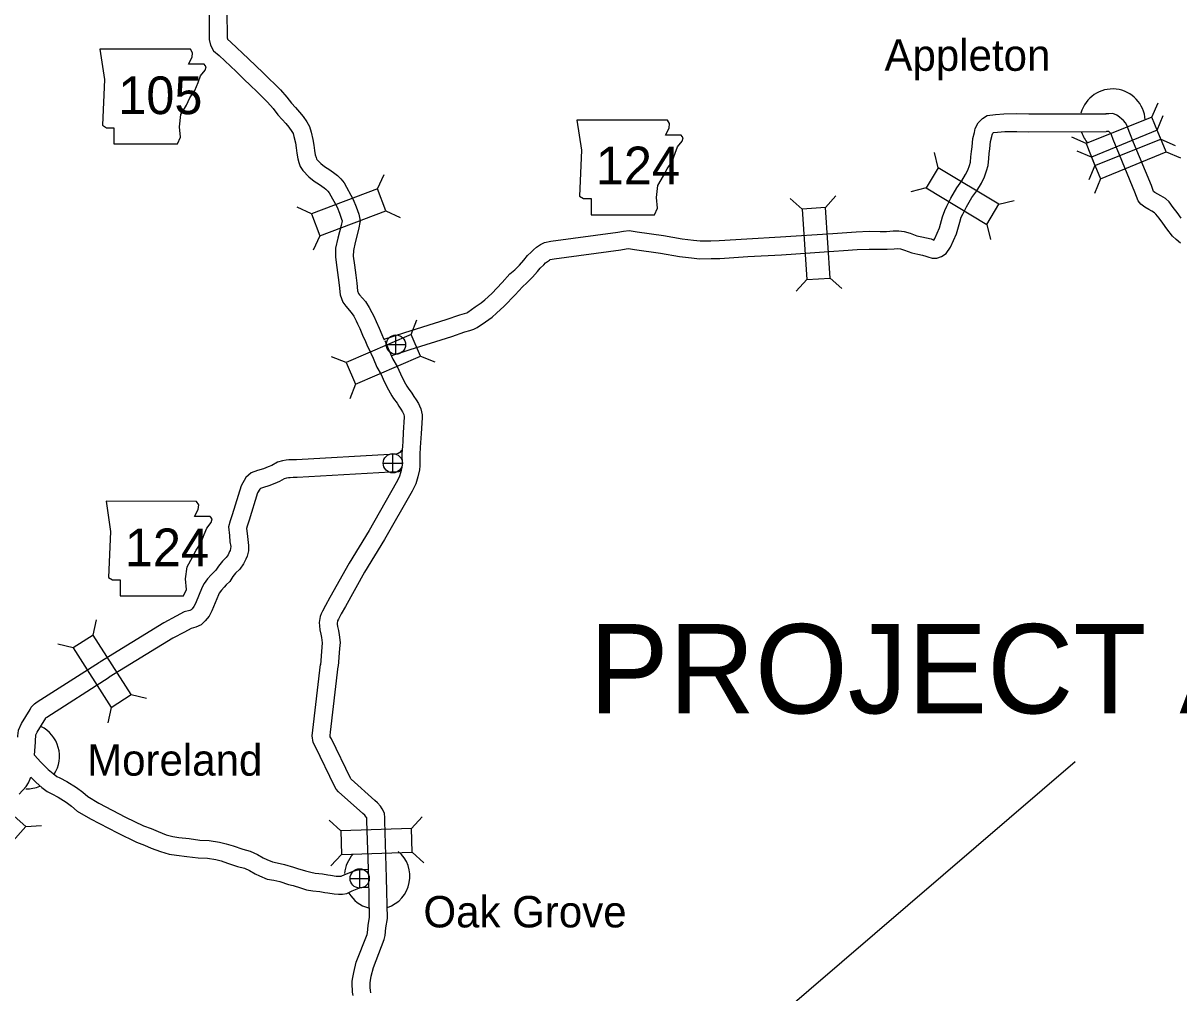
# Model space of a CAD drawing. Extents: x 1374139 to 1377472, y 1168351 to 1170484.
# Drawn here: x 1374734 to 1374928.1, y 1170176.4 to 1170339.4 of the extents above; entities that cross this region are included whole.
import ezdxf

# ---------------------------------------------------------------- set-up
doc = ezdxf.new("R2010")
doc.units = 0
doc.layers.add('15', color=7, linetype='Continuous')
doc.layers.add('Default', color=7, linetype='Continuous')

msp = doc.modelspace()

# ---------------------------------------------------------------- linework, layer by layer
at = {"layer": '15'}
msp.add_line((1374910.7, 1170215.21), (1374680.58, 1170017.86), dxfattribs=at)
at = {"layer": 'Default'}
for p, q in [((1374923.61, 1170323.53), (1374924.65, 1170325.95)), ((1374924.46, 1170321.38), (1374925.47, 1170323.82)), ((1374912.57, 1170319.13), (1374910.15, 1170320.17)), ((1374925.08, 1170319.85), (1374927.5, 1170318.81)), ((1374887.7, 1170315.05), (1374887.06, 1170317.61)), ((1374913.48, 1170316.85), (1374911.04, 1170317.86)), ((1374925.97, 1170317.72), (1374928.41, 1170316.71)), ((1374914.04, 1170315.45), (1374913, 1170313.02)), ((1374793.52, 1170311.5), (1374794.61, 1170313.91)), ((1374914.99, 1170313.19), (1374913.98, 1170310.75)), ((1374885.66, 1170311.66), (1374883.1, 1170311.02)), ((1374864.83, 1170308.12), (1374862.85, 1170309.87)), ((1374868.78, 1170308.38), (1374870.52, 1170310.36)), ((1374897.88, 1170308.93), (1374900.44, 1170309.57)), ((1374782.39, 1170307.32), (1374779.99, 1170308.41)), ((1374794.91, 1170307.8), (1374797.31, 1170306.71)), ((1374895.84, 1170305.54), (1374896.48, 1170302.98)), ((1374783.79, 1170303.62), (1374782.7, 1170301.21)), ((1374865.6, 1170296.27), (1374863.86, 1170294.29)), ((1374869.55, 1170296.52), (1374871.53, 1170294.78)), ((1374799.13, 1170287.04), (1374800.1, 1170289.49)), ((1374796.59, 1170283.71), (1374796.59, 1170286.96)), ((1374794.97, 1170285.33), (1374798.22, 1170285.33)), ((1374788.22, 1170282.32), (1374785.77, 1170283.29)), ((1374800.7, 1170283.4), (1374803.15, 1170282.43)), ((1374789.79, 1170278.69), (1374788.82, 1170276.23)), ((1374796.07, 1170263.78), (1374796.07, 1170267.03)), ((1374794.44, 1170265.4), (1374797.69, 1170265.4)), ((1374745.7, 1170236.53), (1374746.27, 1170239.11)), ((1374742.36, 1170234.4), (1374739.78, 1170234.97)), ((1374752.08, 1170226.51), (1374754.66, 1170225.94)), ((1374748.74, 1170224.38), (1374748.17, 1170221.8)), ((1374734.39, 1170204.34), (1374737.03, 1170204.5)), ((1374787.31, 1170203.63), (1374785.38, 1170205.43)), ((1374799.18, 1170204.03), (1374800.99, 1170205.96)), ((1374787.44, 1170199.67), (1374785.64, 1170197.74)), ((1374799.32, 1170200.07), (1374801.25, 1170198.27)), ((1374790.5, 1170194.01), (1374790.5, 1170197.26)), ((1374788.87, 1170195.63), (1374792.12, 1170195.63))]:
    msp.add_line(p, q, dxfattribs=at)
for points in [[(1374765.19, 1170341.33), (1374765.23, 1170336.62), (1374765.41, 1170335.64), (1374765.95, 1170334.69), (1374766.87, 1170333.93), (1374769.73, 1170331.2), (1374770.96, 1170330.01), (1374772.22, 1170328.84), (1374773.14, 1170327.91), (1374774.16, 1170326.9), (1374775.01, 1170326.06), (1374775.97, 1170325.01), (1374776.77, 1170323.95), (1374777.49, 1170323.18), (1374778.09, 1170322.48), (1374778.61, 1170321.85), (1374779.12, 1170321.13), (1374779.31, 1170320.79), (1374779.46, 1170320.28), (1374779.69, 1170319.23), (1374779.84, 1170318.41), (1374779.94, 1170317.51), (1374780.12, 1170316.54), (1374780.3, 1170315.91), (1374780.5, 1170315.27), (1374780.93, 1170314.57), (1374781.96, 1170313.51), (1374782.86, 1170312.82), (1374783.76, 1170312.26), (1374784.51, 1170311.68), (1374784.82, 1170311.45), (1374785.14, 1170311.14), (1374785.4, 1170310.84), (1374786.71, 1170308.43), (1374787.1, 1170307.42), (1374787.47, 1170306.43), (1374787.54, 1170306.12), (1374787.39, 1170305.33), (1374786.84, 1170303.23), (1374786.45, 1170301.55), (1374786.42, 1170300.04), (1374786.65, 1170298.3), (1374786.87, 1170296.62), (1374787.04, 1170295.31), (1374787.21, 1170293.67), (1374787.67, 1170292.48), (1374788.15, 1170291.82), (1374789.08, 1170290.75), (1374789.5, 1170290.09), (1374789.89, 1170289.34), (1374790.16, 1170288.83), (1374790.52, 1170288.03), (1374791, 1170286.92), (1374791.45, 1170285.87), (1374791.82, 1170285.01), (1374792.03, 1170284.65)], [(1374768.19, 1170341.35), (1374768.22, 1170336.91), (1374768.27, 1170336.69), (1374768.29, 1170336.65), (1374768.87, 1170336.17), (1374771.81, 1170333.36), (1374773.03, 1170332.19), (1374774.3, 1170330.99), (1374775.26, 1170330.04), (1374776.28, 1170329.03), (1374777.17, 1170328.13), (1374778.28, 1170326.93), (1374779.07, 1170325.88), (1374779.72, 1170325.18), (1374780.39, 1170324.41), (1374781, 1170323.66), (1374781.64, 1170322.75), (1374782.09, 1170321.98), (1374782.37, 1170321.02), (1374782.64, 1170319.81), (1374782.81, 1170318.84), (1374782.91, 1170317.96), (1374783.04, 1170317.22), (1374783.17, 1170316.77), (1374783.25, 1170316.53), (1374783.31, 1170316.42), (1374783.96, 1170315.76), (1374784.57, 1170315.28), (1374785.47, 1170314.73), (1374786.31, 1170314.08), (1374786.75, 1170313.76), (1374787.34, 1170313.19), (1374787.89, 1170312.53), (1374789.43, 1170309.7), (1374789.9, 1170308.49), (1374790.36, 1170307.27), (1374790.59, 1170306.14), (1374790.31, 1170304.68), (1374789.75, 1170302.51), (1374789.44, 1170301.17), (1374789.42, 1170300.21), (1374789.62, 1170298.69), (1374789.84, 1170297.01), (1374790.02, 1170295.67), (1374790.16, 1170294.37), (1374790.32, 1170293.93), (1374790.49, 1170293.7), (1374791.49, 1170292.55), (1374792.11, 1170291.59), (1374792.56, 1170290.72), (1374792.85, 1170290.14), (1374793.26, 1170289.24), (1374793.75, 1170288.11), (1374794.21, 1170287.06), (1374794.51, 1170286.34), (1374794.64, 1170286.12)], [(1374794.64, 1170286.27), (1374798.06, 1170287.36), (1374805.04, 1170289.54), (1374807.3, 1170290.33), (1374808.09, 1170290.54), (1374808.49, 1170290.69), (1374808.66, 1170290.78), (1374809.92, 1170291.66), (1374810.92, 1170292.33), (1374811.51, 1170292.83), (1374812.68, 1170293.91), (1374814.44, 1170295.76), (1374815.74, 1170297.21), (1374816.54, 1170297.9), (1374817.33, 1170298.7), (1374818.06, 1170299.55), (1374818.67, 1170300.28), (1374819.33, 1170300.88), (1374819.7, 1170301.26), (1374820.22, 1170301.7), (1374820.88, 1170302.16), (1374821.57, 1170302.47), (1374822.63, 1170302.71), (1374833.87, 1170304.22), (1374834.85, 1170304.41), (1374835.77, 1170304.5), (1374837.12, 1170304.29), (1374841.53, 1170303.66), (1374844.68, 1170303.09), (1374846.57, 1170302.88), (1374847.71, 1170302.77), (1374849.5, 1170302.8), (1374850.9, 1170302.82), (1374855.54, 1170303.11), (1374861.18, 1170303.44), (1374869.98, 1170304.01), (1374871.58, 1170304.11), (1374873.9, 1170304.29), (1374876.08, 1170304.39), (1374877.93, 1170304.36), (1374879.03, 1170304.36), (1374880.14, 1170304.45), (1374881.09, 1170304.48), (1374882, 1170304.34), (1374882.96, 1170304.06), (1374884.13, 1170303.63), (1374884.92, 1170303.44), (1374885.71, 1170303.28), (1374886.5, 1170303.09), (1374886.97, 1170302.91), (1374887.12, 1170303.14), (1374887.92, 1170304.97), (1374888.44, 1170306.8), (1374888.79, 1170307.85), (1374889.12, 1170308.58), (1374889.81, 1170309.94), (1374890.85, 1170311.67), (1374891.67, 1170312.83), (1374892.31, 1170313.91), (1374892.68, 1170314.67), (1374892.95, 1170315.43), (1374893.11, 1170316), (1374893.19, 1170316.89), (1374893.29, 1170317.79), (1374893.38, 1170318.57), (1374893.54, 1170319.95), (1374893.77, 1170320.99), (1374893.93, 1170321.66), (1374894.42, 1170322.62), (1374895.12, 1170323.34), (1374895.94, 1170323.86), (1374897.34, 1170324.01), (1374898.72, 1170324.14), (1374900.91, 1170324.16), (1374902.9, 1170324.11), (1374915.93, 1170324.12)], [(1374928.51, 1170306.57), (1374927.85, 1170307.51), (1374927.2, 1170308.38), (1374926.48, 1170309.33), (1374925.86, 1170309.88), (1374925.1, 1170310.35), (1374924.57, 1170310.64), (1374924.12, 1170310.92), (1374923.88, 1170311.09), (1374923.51, 1170312.05), (1374920.52, 1170319.3), (1374919.89, 1170320.87), (1374919.63, 1170321.61), (1374919.46, 1170322.07), (1374919.15, 1170322.59), (1374918.81, 1170322.97), (1374918.55, 1170323.22), (1374918.17, 1170323.58), (1374917.71, 1170323.89), (1374917.03, 1170324.15), (1374916.37, 1170324.14), (1374915.87, 1170324.12)], [(1374795.88, 1170283.51), (1374798.97, 1170284.5), (1374805.98, 1170286.69), (1374808.19, 1170287.46), (1374809.01, 1170287.68), (1374809.7, 1170287.94), (1374810.22, 1170288.21), (1374811.62, 1170289.18), (1374812.74, 1170289.93), (1374813.51, 1170290.6), (1374814.78, 1170291.77), (1374816.64, 1170293.72), (1374817.85, 1170295.06), (1374818.59, 1170295.71), (1374819.54, 1170296.67), (1374820.35, 1170297.62), (1374820.84, 1170298.2), (1374821.42, 1170298.73), (1374821.74, 1170299.06), (1374822.04, 1170299.31), (1374822.38, 1170299.55), (1374822.53, 1170299.61), (1374823.16, 1170299.75), (1374834.36, 1170301.26), (1374835.28, 1170301.43), (1374835.69, 1170301.47), (1374836.68, 1170301.33), (1374841.05, 1170300.7), (1374844.24, 1170300.13), (1374846.27, 1170299.89), (1374847.6, 1170299.77), (1374849.54, 1170299.8), (1374851.01, 1170299.82), (1374855.73, 1170300.12), (1374861.36, 1170300.44), (1374870.17, 1170301.01), (1374871.79, 1170301.12), (1374874.09, 1170301.29), (1374876.12, 1170301.39), (1374877.9, 1170301.36), (1374879.15, 1170301.35), (1374880.32, 1170301.45), (1374880.91, 1170301.47), (1374881.34, 1170301.41), (1374882.02, 1170301.21), (1374883.27, 1170300.75), (1374884.28, 1170300.51), (1374885.05, 1170300.35), (1374885.61, 1170300.22), (1374885.96, 1170300.08), (1374886.67, 1170299.84), (1374887.49, 1170299.88), (1374888.23, 1170300.13), (1374889.06, 1170300.63), (1374889.77, 1170301.7), (1374890.75, 1170303.96), (1374891.31, 1170305.92), (1374891.58, 1170306.75), (1374891.82, 1170307.28), (1374892.43, 1170308.49), (1374893.36, 1170310.03), (1374894.18, 1170311.19), (1374894.95, 1170312.48), (1374895.45, 1170313.51), (1374895.81, 1170314.52), (1374896.07, 1170315.44), (1374896.18, 1170316.6), (1374896.27, 1170317.45), (1374896.36, 1170318.22), (1374896.5, 1170319.46), (1374896.69, 1170320.31), (1374896.76, 1170320.61), (1374896.89, 1170320.85), (1374896.99, 1170320.95), (1374897.64, 1170321.02), (1374898.88, 1170321.14), (1374900.89, 1170321.16), (1374902.86, 1170321.11), (1374915.93, 1170321.12)], [(1374928.38, 1170302.37), (1374927.68, 1170302.97), (1374927.07, 1170303.55), (1374926.1, 1170304.78), (1374925.42, 1170305.74), (1374924.8, 1170306.57), (1374924.27, 1170307.28), (1374924.05, 1170307.47), (1374923.6, 1170307.75), (1374923.07, 1170308.03), (1374922.43, 1170308.43), (1374921.75, 1170308.94), (1374921.27, 1170309.51), (1374920.73, 1170310.94), (1374917.74, 1170318.17), (1374917.08, 1170319.82), (1374916.81, 1170320.59), (1374916.74, 1170320.77), (1374916.73, 1170320.8), (1374916.65, 1170320.88), (1374916.47, 1170321.06), (1374916.39, 1170321.13), (1374915.99, 1170321.12)], [(1374794.7, 1170286), (1374795.48, 1170284.28), (1374796.08, 1170282.9), (1374796.78, 1170281.68), (1374797.35, 1170280.41), (1374797.98, 1170279.11), (1374798.41, 1170278.34), (1374798.63, 1170278.03), (1374799.26, 1170277.16), (1374799.61, 1170276.61), (1374799.97, 1170276.08), (1374800.36, 1170275.43), (1374800.54, 1170275.06), (1374800.76, 1170274.54), (1374800.98, 1170273.56), (1374800.97, 1170273.03), (1374800.81, 1170270.39), (1374800.73, 1170268.85), (1374800.66, 1170268.05), (1374800.59, 1170266.95), (1374800.61, 1170264.98), (1374800.56, 1170264.28), (1374800.28, 1170263.13), (1374799.91, 1170261.96), (1374799.32, 1170260.7), (1374794.67, 1170252.6), (1374791.33, 1170247.09), (1374788.1, 1170241.35), (1374787.4, 1170240.09), (1374786.94, 1170239.19), (1374786.79, 1170238.9), (1374786.79, 1170238.89), (1374786.71, 1170238.47), (1374786.72, 1170238.35), (1374786.77, 1170237.95), (1374786.93, 1170237.32), (1374787.06, 1170236.57), (1374787.2, 1170235.26), (1374787.12, 1170234.25), (1374786.89, 1170231.29)], [(1374791.97, 1170284.76), (1374792.74, 1170283.06), (1374793.39, 1170281.56), (1374794.1, 1170280.31), (1374794.63, 1170279.14), (1374795.32, 1170277.71), (1374795.88, 1170276.72), (1374796.2, 1170276.28), (1374796.78, 1170275.47), (1374797.1, 1170274.97), (1374797.44, 1170274.47), (1374797.71, 1170274.01), (1374797.81, 1170273.81), (1374797.9, 1170273.61), (1374797.97, 1170273.25), (1374797.97, 1170273.14), (1374797.81, 1170270.55), (1374797.74, 1170269.06), (1374797.67, 1170268.28), (1374797.59, 1170267.03), (1374797.61, 1170265.07), (1374797.59, 1170264.75), (1374797.39, 1170263.94), (1374797.11, 1170263.06), (1374796.65, 1170262.09), (1374792.09, 1170254.12), (1374788.74, 1170248.61), (1374785.48, 1170242.81), (1374784.76, 1170241.51), (1374784.27, 1170240.56), (1374784.02, 1170240.07), (1374783.87, 1170239.63), (1374783.7, 1170238.65), (1374783.73, 1170238.07), (1374783.82, 1170237.39), (1374783.99, 1170236.7), (1374784.09, 1170236.14), (1374784.19, 1170235.21), (1374784.13, 1170234.49), (1374783.9, 1170231.52)], [(1374797.65, 1170267.6), (1374797.49, 1170267.46), (1374797.22, 1170267.2), (1374797.22, 1170267.2), (1374796.94, 1170267.05), (1374796.57, 1170266.95), (1374795.49, 1170266.88), (1374779.9, 1170265.99), (1374779.23, 1170265.98), (1374778.62, 1170265.95), (1374778.15, 1170265.9), (1374777.56, 1170265.8), (1374776.67, 1170265.56), (1374775.72, 1170265.03), (1374775.14, 1170264.78), (1374774.32, 1170264.48), (1374773.35, 1170264.19), (1374772.27, 1170263.77), (1374771.38, 1170263), (1374770.57, 1170261.6), (1374769.09, 1170256.73), (1374768.73, 1170255.7), (1374768.47, 1170254.71), (1374768.6, 1170253.28), (1374768.71, 1170252.19), (1374768.83, 1170251.39), (1374768.82, 1170251.07), (1374768.74, 1170250.74), (1374768.65, 1170250.54), (1374768.39, 1170249.99), (1374768.09, 1170249.55), (1374767.43, 1170248.93), (1374766.77, 1170248.1), (1374766.33, 1170247.42), (1374766, 1170247.1), (1374765.54, 1170246.65), (1374764.93, 1170245.97), (1374764.36, 1170245.18), (1374764.04, 1170244.56), (1374762.91, 1170241.85), (1374762.65, 1170241.33), (1374762.34, 1170240.93), (1374762.18, 1170240.78), (1374761.94, 1170240.68), (1374761.02, 1170240.41), (1374759.65, 1170239.68), (1374757.61, 1170238.59), (1374746.83, 1170231.98)], [(1374797.38, 1170264.06), (1374797.08, 1170263.98), (1374795.69, 1170263.88), (1374780.02, 1170262.99), (1374779.33, 1170262.98), (1374778.84, 1170262.96), (1374778.56, 1170262.93), (1374778.21, 1170262.87), (1374777.81, 1170262.76), (1374777.04, 1170262.33), (1374776.24, 1170261.99), (1374775.26, 1170261.63), (1374774.32, 1170261.35), (1374773.84, 1170261.16), (1374773.73, 1170261.06), (1374773.34, 1170260.4), (1374771.94, 1170255.81), (1374771.6, 1170254.82), (1374771.5, 1170254.44), (1374771.58, 1170253.58), (1374771.69, 1170252.57), (1374771.84, 1170251.57), (1374771.81, 1170250.67), (1374771.6, 1170249.79), (1374771.38, 1170249.28), (1374770.98, 1170248.47), (1374770.39, 1170247.61), (1374769.65, 1170246.9), (1374769.21, 1170246.34), (1374768.66, 1170245.5), (1374768.08, 1170244.94), (1374767.71, 1170244.58), (1374767.27, 1170244.08), (1374766.91, 1170243.59), (1374766.76, 1170243.29), (1374765.65, 1170240.61), (1374765.2, 1170239.71), (1374764.56, 1170238.9), (1374763.87, 1170238.25), (1374762.97, 1170237.85), (1374762.16, 1170237.62), (1374761.06, 1170237.03), (1374759.1, 1170235.99), (1374748.4, 1170229.43)], [(1374733.04, 1170219.38), (1374733.09, 1170219.67), (1374733.1, 1170220), (1374733.17, 1170220.57), (1374733.67, 1170221.64), (1374735.14, 1170224.02), (1374735.33, 1170224.39), (1374735.84, 1170224.99), (1374736.32, 1170225.29), (1374746.81, 1170231.97)], [(1374789.41, 1170175.95), (1374789.32, 1170176.49), (1374789.28, 1170177.04), (1374789.26, 1170177.52), (1374789.25, 1170178.36), (1374789.37, 1170178.98), (1374789.5, 1170179.82), (1374789.93, 1170181.58), (1374791.75, 1170186.23), (1374791.82, 1170186.51), (1374791.92, 1170187.71), (1374792.14, 1170189.12), (1374792.02, 1170195.63), (1374791.7, 1170205.29), (1374791.72, 1170205.77), (1374791.7, 1170205.82), (1374791.61, 1170205.93), (1374791.34, 1170206.24), (1374791.01, 1170206.56), (1374786.95, 1170210.17), (1374786.56, 1170210.61), (1374786.27, 1170211.14), (1374783.07, 1170217.74), (1374782.69, 1170218.48), (1374782.5, 1170219.57), (1374782.62, 1170220.57), (1374783.91, 1170231.57)], [(1374735.89, 1170216.33), (1374736.04, 1170218.53), (1374736.03, 1170219.08), (1374736.08, 1170219.38), (1374736.09, 1170219.74), (1374736.31, 1170220.21), (1374737.77, 1170222.56), (1374737.84, 1170222.7), (1374737.92, 1170222.75), (1374748.42, 1170229.44)], [(1374792.37, 1170176.43), (1374792.3, 1170176.85), (1374792.27, 1170177.22), (1374792.26, 1170177.58), (1374792.26, 1170178.1), (1374792.33, 1170178.48), (1374792.44, 1170179.23), (1374792.8, 1170180.67), (1374794.63, 1170185.35), (1374794.79, 1170186.05), (1374794.9, 1170187.35), (1374795.15, 1170188.91), (1374795.02, 1170195.71), (1374794.7, 1170205.28), (1374794.72, 1170205.87), (1374794.65, 1170206.54), (1374794.49, 1170206.93), (1374794.3, 1170207.33), (1374793.97, 1170207.8), (1374793.51, 1170208.31), (1374793.07, 1170208.75), (1374789.07, 1170212.31), (1374789.03, 1170212.34), (1374788.94, 1170212.5), (1374785.75, 1170219.09), (1374785.56, 1170219.45), (1374785.53, 1170219.64), (1374785.6, 1170220.21), (1374786.89, 1170231.23)], [(1374735.89, 1170216.33), (1374736.93, 1170215.16), (1374738.18, 1170213.96), (1374738.99, 1170213.24), (1374739.61, 1170212.77), (1374740.1, 1170212.52), (1374741.31, 1170211.93), (1374742.9, 1170210.91), (1374743.97, 1170210.11), (1374744.82, 1170209.39), (1374746.7, 1170208.27), (1374751.16, 1170205.95), (1374754.18, 1170204.49), (1374755.46, 1170204.02), (1374756.63, 1170203.49), (1374757.97, 1170202.98), (1374759.1, 1170202.66), (1374760.11, 1170202.52), (1374761.86, 1170202.32), (1374763.62, 1170202.08), (1374765.23, 1170202), (1374766.96, 1170201.74), (1374768.04, 1170201.45), (1374769.24, 1170201.08), (1374770.86, 1170200.54), (1374772.12, 1170200.19), (1374773.35, 1170199.65), (1374774.3, 1170199.09), (1374774.91, 1170198.82), (1374775.85, 1170198.4), (1374776.65, 1170198.25), (1374777.85, 1170197.99), (1374779.36, 1170197.5), (1374780.07, 1170197.32), (1374781.42, 1170196.93), (1374782.29, 1170196.66), (1374783.02, 1170196.54), (1374784.27, 1170196.41), (1374785.14, 1170196.23), (1374785.61, 1170196.16), (1374786.53, 1170196.01), (1374786.99, 1170195.99), (1374787.4, 1170195.99), (1374787.41, 1170195.99), (1374788.03, 1170196.29), (1374789.27, 1170196.78), (1374789.96, 1170197.03), (1374790.7, 1170197.13), (1374791.18, 1170197.15), (1374792, 1170197.16)], [(1374733.3, 1170209.8), (1374734.45, 1170211.06), (1374734.83, 1170211.7), (1374735.13, 1170212.36), (1374735.23, 1170212.63)], [(1374735.23, 1170212.63), (1374736.15, 1170211.75), (1374737.1, 1170210.91), (1374738.01, 1170210.23), (1374738.75, 1170209.84), (1374739.84, 1170209.31), (1374741.19, 1170208.44), (1374742.1, 1170207.77), (1374743.06, 1170206.94), (1374745.25, 1170205.65), (1374749.81, 1170203.27), (1374753.01, 1170201.72), (1374754.32, 1170201.24), (1374755.47, 1170200.72), (1374757.02, 1170200.13), (1374758.49, 1170199.71), (1374759.74, 1170199.54), (1374761.48, 1170199.34), (1374763.34, 1170199.09), (1374764.93, 1170199.01), (1374766.35, 1170198.8), (1374767.2, 1170198.57), (1374768.31, 1170198.22), (1374769.98, 1170197.66), (1374771.12, 1170197.35), (1374771.97, 1170196.98), (1374772.92, 1170196.42), (1374773.69, 1170196.07), (1374774.95, 1170195.52), (1374776.05, 1170195.31), (1374777.07, 1170195.09), (1374778.55, 1170194.61), (1374779.3, 1170194.43), (1374780.54, 1170194.06), (1374781.59, 1170193.73), (1374782.63, 1170193.56), (1374783.82, 1170193.44), (1374784.63, 1170193.28), (1374785.16, 1170193.2), (1374786.2, 1170193.02), (1374786.92, 1170192.99), (1374787.64, 1170192.99), (1374788.33, 1170193.1), (1374789.24, 1170193.54), (1374790.34, 1170193.98), (1374790.68, 1170194.1), (1374790.96, 1170194.14), (1374791.26, 1170194.15), (1374791.95, 1170194.16)]]:
    msp.add_lwpolyline(points, dxfattribs=at)
for points in [[(1374746.85, 1170334.98), (1374747.61, 1170329.91), (1374747.27, 1170322.21), (1374747.95, 1170321.78), (1374749.21, 1170321.78), (1374749.21, 1170319.08), (1374759.87, 1170319.08), (1374760.38, 1170320.18), (1374760.21, 1170321.95), (1374760.47, 1170323.98), (1374761.4, 1170325.59), (1374761.99, 1170326.78), (1374762.83, 1170328.04), (1374763.34, 1170329.4), (1374763.76, 1170330.5), (1374764.53, 1170331.43), (1374764.69, 1170332.02), (1374764.36, 1170332.44), (1374761.73, 1170332.44), (1374762.33, 1170333.63), (1374762.41, 1170334.39), (1374762.06, 1170334.97)], [(1374827, 1170323.06), (1374827.76, 1170317.99), (1374827.43, 1170310.29), (1374828.1, 1170309.87), (1374829.37, 1170309.87), (1374829.37, 1170307.16), (1374840.03, 1170307.16), (1374840.54, 1170308.26), (1374840.37, 1170310.04), (1374840.62, 1170312.07), (1374841.55, 1170313.67), (1374842.14, 1170314.86), (1374842.99, 1170316.13), (1374843.5, 1170317.48), (1374843.92, 1170318.58), (1374844.68, 1170319.51), (1374844.85, 1170320.1), (1374844.51, 1170320.53), (1374841.89, 1170320.53), (1374842.48, 1170321.71), (1374842.57, 1170322.47), (1374842.22, 1170323.06)], [(1374923.61, 1170323.53), (1374912.57, 1170319.13), (1374914.04, 1170315.45), (1374925.08, 1170319.85)], [(1374924.46, 1170321.38), (1374913.48, 1170316.85), (1374914.99, 1170313.19), (1374925.97, 1170317.72)], [(1374885.66, 1170311.66), (1374895.84, 1170305.54), (1374897.88, 1170308.93), (1374887.7, 1170315.05)], [(1374793.52, 1170311.5), (1374782.39, 1170307.32), (1374783.79, 1170303.62), (1374794.91, 1170307.8)], [(1374864.83, 1170308.12), (1374865.6, 1170296.27), (1374869.55, 1170296.52), (1374868.78, 1170308.38)], [(1374799.13, 1170287.04), (1374788.22, 1170282.32), (1374789.79, 1170278.69), (1374800.7, 1170283.4)], [(1374747.88, 1170259), (1374748.64, 1170253.92), (1374748.31, 1170246.22), (1374748.98, 1170245.8), (1374750.25, 1170245.8), (1374750.25, 1170243.09), (1374760.91, 1170243.09), (1374761.42, 1170244.19), (1374761.25, 1170245.97), (1374761.5, 1170248), (1374762.43, 1170249.61), (1374763.02, 1170250.79), (1374763.87, 1170252.06), (1374764.38, 1170253.41), (1374764.8, 1170254.51), (1374765.56, 1170255.44), (1374765.73, 1170256.04), (1374765.39, 1170256.46), (1374762.77, 1170256.46), (1374763.36, 1170257.64), (1374763.45, 1170258.4), (1374763.1, 1170258.99)], [(1374742.36, 1170234.4), (1374748.74, 1170224.38), (1374752.08, 1170226.51), (1374745.7, 1170236.53)], [(1374722.88, 1170209.26), (1374731.76, 1170201.38), (1374734.39, 1170204.34), (1374725.5, 1170212.22)], [(1374787.44, 1170199.67), (1374799.32, 1170200.07), (1374799.18, 1170204.03), (1374787.31, 1170203.63)]]:
    msp.add_lwpolyline(points, close=True, dxfattribs=at)
for centre in [(1374796.59, 1170285.33), (1374796.07, 1170265.4), (1374790.5, 1170195.63)]:
    msp.add_circle(centre, 1.62, dxfattribs=at)
for centre, start, end in [((1374916.99, 1170322.79), 3.0493, 164.6743), ((1374916.99, 1170322.79), 198.8091, 221.3437), ((1374734.57, 1170216.18), 326.6822, 64.3501), ((1374734.57, 1170216.18), 268.1486, 293.6276), ((1374793.43, 1170195.97), 137.3818, 174.7553), ((1374793.43, 1170195.97), 288.4119, 49.6434), ((1374793.43, 1170195.97), 210.7252, 254.7143)]:
    msp.add_arc(centre, 5.5, start, end, dxfattribs=at)

# ---------------------------------------------------------------- texts
for s, height, p in [('Appleton', 5.28, (1374878.67, 1170331.34)), ('105', 6.336, (1374749.94, 1170324.06)), ('124', 6.336, (1374830.18, 1170312.27)), ('124', 6.336, (1374751.05, 1170248.09)), ('PROJECT AREA', 15, (1374829.04, 1170223.37)), ('Moreland', 5.28, (1374744.71, 1170212.9)), ('Oak Grove', 5.28, (1374801.21, 1170187.4))]:
    msp.add_text(s, height=height, dxfattribs=at).set_placement(p)

doc.saveas('drawing.dxf')
